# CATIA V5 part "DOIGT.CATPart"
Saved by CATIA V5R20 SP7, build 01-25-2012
Part number: DOIGT
Bounding box of the stored display mesh (mm): x -42 to 22, y -12 to 12, z 17.345 to 229.345
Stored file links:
  J:\IAO_placube\DOIGT.CATPart
  C:\Users\LACUBE\Desktop\Courant\Projet IAO\essai du 0212\Ass_IAO.CATProduct
  J:\IAO_placube\SKL_general.CATPart
  J:\IAO_placube\SKL_doigt.CATPart
  J:\IAO_placube\placube_assemblage_IAO.CATProduct
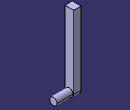
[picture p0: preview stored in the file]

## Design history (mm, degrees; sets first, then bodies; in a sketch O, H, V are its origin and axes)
Set1
  Plane1 "plan_ref": linked copy from another document
  Sketch1, origin (0, 0, 0), H (0, 1, 0), V (0, 0, 1), geometry linked from another document
Body1 (main body)
  Sketch2 on Plane1, origin (0, 0, 0), H (0, 1, 0), V (0, 0, 1)
    circle A1 centre (0, 29.3446) radius 10
    point P1 (0, 29.3446)
    reference projected point E1 (0, 29.3446) from Sketch1
    radius A1 = 10
    coincidence: P1 E1
  Pad1: profile Sketch2, direction (1, 0, 0), length 22, mirrored extent
  Sketch3 on start face of Pad1, origin (-22, 0, 0), H (0, -1, 0), V (0, 0, 1)
    arc A1 centre (0, 29.3446) radius 12 from (-12, 29.3446) to (12, 29.3446) ccw
    reference projected circle E1 centre (0, 29.3446) radius 10 from edge [start face of Pad1 | face of Pad1 from Sketch2.A1]
    line L1 (-12, 29.3446) -> (-12, 229.3446)
    line L2 (12, 29.3446) -> (12, 229.3446)
    line L3 (-12, 229.3446) -> (12, 229.3446)
    reference projected point E2 (0, 29.3446) from Sketch1
    radius A1 = 12
    distance E2 L3 = 200
    concentricity: A1 E1
    tangency: L1 A1, L2 A1
    horizontal: L3 H
    perpendicularity: L3 L1, L2 L3
  Pad2: profile Sketch3, direction (-1, 0, 0), length 20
